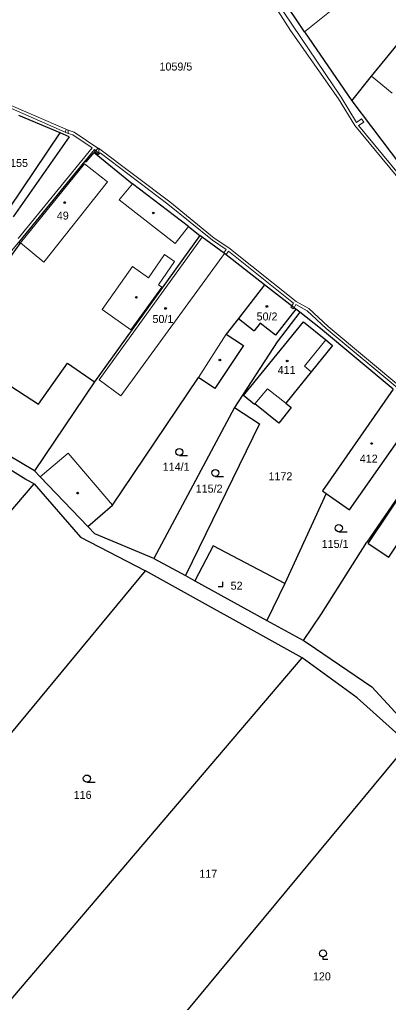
# Model space of a CAD drawing. Extents: x -694609 to -690140, y -1033292 to -1029794.
# Drawn here: x -692687.4 to -692609.2, y -1031527.4 to -1031318.8 of the extents above; entities that cross this region are included whole.
import ezdxf
from ezdxf.enums import TextEntityAlignment as Align

# ---------------------------------------------------------------- set-up
doc = ezdxf.new("R2010")
doc.units = 0
doc.header["$LTSCALE"] = 0.68
for name, color, linetype, lineweight in [('1', 7, 'Continuous', 25), ('13', 7, 'Continuous', 13), ('3', 7, 'Continuous', 25), ('4', 7, 'Continuous', 13), ('5', 7, 'Continuous', 25)]:
    doc.layers.add(name, color=color, linetype=linetype, lineweight=lineweight)
doc.layers.add('2', color=7, linetype='Continuous')

msp = doc.modelspace()

# ---------------------------------------------------------------- linework, layer by layer
at = {"layer": '1'}
for p, q in [((-692626.97, -1031321.4), (-692635.9, -1031307.93)), ((-692612.71, -1031330.82), (-692599.81, -1031314.84)), ((-692626.97, -1031321.4), (-692616.92, -1031336.03)), ((-692616.92, -1031336.03), (-692612.71, -1031330.82)), ((-692616.92, -1031336.03), (-692602.08, -1031355.67)), ((-692678.77, -1031342.85), (-692687.56, -1031339.16)), ((-692689.54, -1031358.81), (-692678.77, -1031342.85)), ((-692676.85, -1031343.68), (-692688.71, -1031360.64)), ((-692676.85, -1031343.68), (-692678.77, -1031342.85)), ((-692673.28, -1031348.98), (-692671.59, -1031346.97)), ((-692671.59, -1031346.97), (-692663.44, -1031353.61)), ((-692673.46, -1031348.86), (-692673.28, -1031348.98)), ((-692651.55, -1031362.7), (-692663.44, -1031353.61)), ((-692649.13, -1031364.63), (-692671.47, -1031395.68)), ((-692651.55, -1031362.7), (-692649.13, -1031364.63)), ((-692648.65, -1031364.98), (-692649.13, -1031364.63)), ((-692643.93, -1031368.4), (-692648.65, -1031364.98)), ((-692635.41, -1031375.06), (-692643.93, -1031368.4)), ((-692635.41, -1031375.06), (-692640.93, -1031382.21)), ((-692628.78, -1031380.24), (-692635.41, -1031375.06)), ((-692628.78, -1031380.24), (-692633.07, -1031385.75)), ((-692627.94, -1031380.9), (-692632.77, -1031387.19)), ((-692627.94, -1031380.9), (-692628.78, -1031380.24)), ((-692623.54, -1031384.37), (-692627.94, -1031380.9)), ((-692640.93, -1031382.21), (-692643.56, -1031385.53)), ((-692640.93, -1031382.21), (-692637.61, -1031384.82)), ((-692636.33, -1031383.19), (-692637.61, -1031384.82)), ((-692633.07, -1031385.75), (-692636.33, -1031383.19)), ((-692608.15, -1031397.22), (-692623.54, -1031384.37)), ((-692643.56, -1031385.53), (-692639.89, -1031387.99)), ((-692632.77, -1031387.19), (-692641.8, -1031401.15)), ((-692622.44, -1031386.78), (-692621, -1031387.94)), ((-692639.89, -1031387.99), (-692645.99, -1031397.06)), ((-692621, -1031387.94), (-692625.52, -1031393.53)), ((-692683.35, -1031400.43), (-692677.2, -1031391.74)), ((-692677.2, -1031391.74), (-692671.47, -1031395.68)), ((-692625.52, -1031393.53), (-692630.91, -1031400.19)), ((-692693.28, -1031393.98), (-692683.35, -1031400.43)), ((-692671.47, -1031395.68), (-692684.23, -1031414.56)), ((-692667.66, -1031421.85), (-692649.42, -1031394.75)), ((-692645.99, -1031397.06), (-692649.42, -1031394.75)), ((-692686.06, -1031416.42), (-692716.84, -1031397.3)), ((-692684.23, -1031414.56), (-692710.84, -1031398.79)), ((-692637.58, -1031400.48), (-692639.89, -1031398.59)), ((-692641.8, -1031401.15), (-692658.92, -1031433.17)), ((-692641.8, -1031401.15), (-692636.48, -1031404.59)), ((-692637.48, -1031400.37), (-692637.58, -1031400.48)), ((-692632.43, -1031404.43), (-692637.48, -1031400.37)), ((-692629.75, -1031401.15), (-692632.43, -1031404.43)), ((-692630.91, -1031400.19), (-692629.75, -1031401.15)), ((-692617.38, -1031422.87), (-692602.67, -1031401.79)), ((-692636.48, -1031404.59), (-692652.2, -1031436.79)), ((-692597.67, -1031406.16), (-692613.72, -1031429.74)), ((-692613.47, -1031430), (-692599.55, -1031409.22)), ((-692682.99, -1031415.86), (-692684.23, -1031414.56)), ((-692684.27, -1031417.34), (-692686.06, -1031416.42)), ((-692672.9, -1031426.41), (-692682.99, -1031415.86)), ((-692701.34, -1031437.24), (-692684.27, -1031417.34)), ((-692684.27, -1031417.34), (-692674.45, -1031428.65)), ((-692622.39, -1031419.37), (-692631.11, -1031438.49)), ((-692622.39, -1031419.37), (-692617.38, -1031422.87)), ((-692672.9, -1031426.41), (-692667.66, -1031421.85)), ((-692671.42, -1031427.95), (-692672.9, -1031426.41)), ((-692674.45, -1031428.65), (-692660.69, -1031435.82)), ((-692658.92, -1031433.17), (-692671.42, -1031427.95)), ((-692646.33, -1031430.51), (-692650.23, -1031437.95)), ((-692631.11, -1031438.49), (-692646.33, -1031430.51)), ((-692623.37, -1031444.92), (-692613.72, -1031429.74)), ((-692658.92, -1031433.17), (-692652.2, -1031436.79)), ((-692723.47, -1031511.71), (-692660.69, -1031435.82)), ((-692627.47, -1031454.27), (-692660.69, -1031435.82)), ((-692652.2, -1031436.79), (-692650.23, -1031437.95)), ((-692650.23, -1031437.95), (-692634.92, -1031446.37)), ((-692631.11, -1031438.49), (-692634.92, -1031446.37)), ((-692627.15, -1031450.62), (-692623.37, -1031444.92)), ((-692634.92, -1031446.37), (-692627.15, -1031450.62)), ((-692627.15, -1031450.62), (-692626.4, -1031451.06)), ((-692626.4, -1031451.06), (-692612.7, -1031460.43)), ((-692692.71, -1031530.91), (-692627.47, -1031454.27)), ((-692615.76, -1031462.74), (-692627.47, -1031454.27)), ((-692612.7, -1031460.43), (-692604.27, -1031469.63)), ((-692604.9, -1031472.56), (-692615.76, -1031462.74)), ((-692668.37, -1031549.11), (-692604.9, -1031472.56))]:
    msp.add_line(p, q, dxfattribs=at)
for points in [[(-692696.94, -1031379.7), (-692687.27, -1031366.28), (-692687.51, -1031366.09), (-692673.46, -1031348.86)], [(-692639.89, -1031398.59), (-692627.16, -1031382.95), (-692622.44, -1031386.78)], [(-692608.15, -1031397.22), (-692623.15, -1031418.84), (-692622.39, -1031419.37)], [(-692613.47, -1031430), (-692609.04, -1031432.91), (-692604.1, -1031425.47), (-692604.28, -1031425.39), (-692595.32, -1031412.04), (-692599.55, -1031409.22)]]:
    msp.add_lwpolyline(points, dxfattribs=at)
at = {"layer": '13'}
for points in [[(-692607.05, -1031351.51), (-692615.47, -1031341.28), (-692614.4, -1031340.54), (-692614.88, -1031339.88), (-692615.96, -1031340.63), (-692619.21, -1031335.26), (-692638.05, -1031307.19), (-692636.87, -1031306.38), (-692637.08, -1031306.05), (-692637.2, -1031305.87), (-692638.38, -1031306.69), (-692643.33, -1031299.42), (-692650.36, -1031289.25), (-692648.77, -1031288.14), (-692649.1, -1031287.64)], [(-692638.71, -1031307.28), (-692629.89, -1031321.09), (-692619.71, -1031335.58), (-692616.25, -1031341.28), (-692607.49, -1031351.91)], [(-692747.34, -1031316.81), (-692731.78, -1031322.14), (-692729.99, -1031322.5), (-692723.23, -1031324.8), (-692723.44, -1031326.11), (-692722.86, -1031326.31), (-692722.65, -1031325), (-692719.27, -1031326.16), (-692711.25, -1031329.38), (-692706.79, -1031330.8), (-692707.19, -1031331.92), (-692706.63, -1031332.13), (-692706.22, -1031331), (-692691.48, -1031336.62), (-692677.69, -1031342.7), (-692677.11, -1031342.94), (-692677.07, -1031342.28), (-692691.26, -1031336.06), (-692706.3, -1031330.33), (-692711.05, -1031328.82), (-692719.07, -1031325.6), (-692729.83, -1031321.92), (-692731.62, -1031321.56), (-692747.14, -1031316.25)], [(-692696.57, -1031376.77), (-692687.26, -1031365.69), (-692671.5, -1031346.39), (-692670.56, -1031347.1), (-692670.58, -1031346.23), (-692675.81, -1031342.7), (-692677.51, -1031342.14), (-692677.69, -1031342.7), (-692677.11, -1031342.94), (-692676.08, -1031343.24), (-692671.97, -1031346.02), (-692687.69, -1031365.27)], [(-692671.3, -1031346.55), (-692671.49, -1031346.78), (-692670.66, -1031347.45), (-692670.32, -1031347.03), (-692655.91, -1031357.96), (-692646.45, -1031365.63), (-692643.58, -1031367.59), (-692644.06, -1031368.3), (-692643.93, -1031368.4), (-692643.59, -1031368.67), (-692643.08, -1031367.93), (-692629.29, -1031378.97), (-692629.64, -1031379.57), (-692629.16, -1031379.94), (-692628.77, -1031379.26), (-692626.4, -1031380.58), (-692622.35, -1031384.38), (-692606.72, -1031397.4)], [(-692606.11, -1031397.13), (-692621.95, -1031383.93), (-692626.04, -1031380.1), (-692628.71, -1031378.61), (-692643, -1031367.26), (-692646.09, -1031365.15), (-692655.53, -1031357.48), (-692670.63, -1031346.06), (-692671.3, -1031346.55)]]:
    msp.add_lwpolyline(points, dxfattribs=at)
msp.add_lwpolyline([(-692629.64, -1031379.57), (-692629.83, -1031379.8), (-692629.35, -1031380.18), (-692629.16, -1031379.94)], close=True, dxfattribs=at)
at = {"layer": '3'}
for p, q in [((-692653.493, -1031411.33), (-692651.743, -1031411.33)), ((-692645.873, -1031415.77), (-692644.123, -1031415.77)), ((-692619.673, -1031427.49), (-692617.923, -1031427.49)), ((-692673.113, -1031480.65), (-692671.363, -1031480.65))]:
    msp.add_line(p, q, dxfattribs=at)
for points in [[(-692645.261, -1031439.15), (-692644.26, -1031439.15), (-692644.26, -1031438.15)], [(-692623.04, -1031517.772), (-692623.04, -1031518.27), (-692622.039, -1031518.27)]]:
    msp.add_lwpolyline(points, dxfattribs=at)
for centre in [(-692653.4929, -1031410.5798), (-692645.8729, -1031415.0198), (-692619.6729, -1031426.7398), (-692673.1129, -1031479.8998), (-692623.0393, -1031517.0209)]:
    msp.add_circle(centre, 0.75, dxfattribs=at)
at = {"layer": '4'}
for p, q in [((-692626.97, -1031321.4), (-692621.32, -1031316.87)), ((-692608.37, -1031334.4), (-692612.71, -1031330.82)), ((-692687.17, -1031366.15), (-692673.6, -1031349.37)), ((-692673.6, -1031349.37), (-692668.72, -1031353.2)), ((-692668.72, -1031353.2), (-692682.24, -1031370.28)), ((-692666.26, -1031357.06), (-692663.44, -1031353.61)), ((-692654.37, -1031366.31), (-692666.26, -1031357.06)), ((-692651.55, -1031362.7), (-692654.37, -1031366.31)), ((-692682.24, -1031370.28), (-692687.17, -1031366.15)), ((-692648.65, -1031364.98), (-692670.49, -1031395.27)), ((-692665.88, -1031398.62), (-692643.93, -1031368.4)), ((-692656.63, -1031368.66), (-692660.07, -1031373.58)), ((-692654.5, -1031370.15), (-692656.63, -1031368.66)), ((-692657.94, -1031375.07), (-692654.5, -1031370.15)), ((-692669.86, -1031380.34), (-692663.46, -1031371.2)), ((-692663.46, -1031371.2), (-692660.07, -1031373.58)), ((-692657.21, -1031375.58), (-692663.81, -1031384.66)), ((-692657.94, -1031375.07), (-692657.21, -1031375.58)), ((-692669.86, -1031380.34), (-692663.81, -1031384.66)), ((-692643.56, -1031385.53), (-692649.42, -1031394.75)), ((-692626.97, -1031392.37), (-692622.44, -1031386.78)), ((-692625.52, -1031393.53), (-692626.97, -1031392.37)), ((-692670.49, -1031395.27), (-692665.88, -1031398.62)), ((-692682.99, -1031415.86), (-692677.1, -1031410.82)), ((-692667.66, -1031421.85), (-692677.1, -1031410.82))]:
    msp.add_line(p, q, dxfattribs=at)
msp.add_lwpolyline([(-692637.48, -1031400.37), (-692634.8, -1031397.13), (-692630.91, -1031400.19)], dxfattribs=at)
at = {"layer": '5'}
for centre in [(-692677.8168, -1031357.6192), (-692659.0268, -1031359.8192), (-692662.6168, -1031377.7292), (-692656.4268, -1031380.0992), (-692634.9368, -1031379.6792), (-692644.8968, -1031391.0592), (-692630.6268, -1031391.2492), (-692612.7168, -1031408.7692), (-692675.0568, -1031419.3092)]:
    msp.add_circle(centre, 0.175, dxfattribs=at)

# ---------------------------------------------------------------- texts
at = {"layer": '2'}
for s, p in [('1059/5', (-692654.23, -1031329.595)), ('1155', (-692688.13, -1031350.065)), ('49', (-692678.219, -1031361.235)), ('50/2', (-692634.899, -1031382.655)), ('50/1', (-692656.979, -1031383.185)), ('411', (-692630.759, -1031394.022)), ('412', (-692613.329, -1031412.835)), ('114/1', (-692654.18, -1031414.555)), ('1172', (-692632.06, -1031416.575)), ('115/2', (-692647.18, -1031419.195)), ('115/1', (-692620.46, -1031430.935)), ('52', (-692641.359, -1031439.805)), ('116', (-692674.009, -1031484.215)), ('117', (-692647.359, -1031500.955)), ('120', (-692623.269, -1031522.745))]:
    msp.add_text(s, height=1.7, dxfattribs=at).set_placement(p, align=Align.CENTER)

doc.saveas('drawing.dxf')
